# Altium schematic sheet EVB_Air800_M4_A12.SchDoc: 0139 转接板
size 840 x 594 mm; REV: 1.0; DESIGNER: LouKangHua
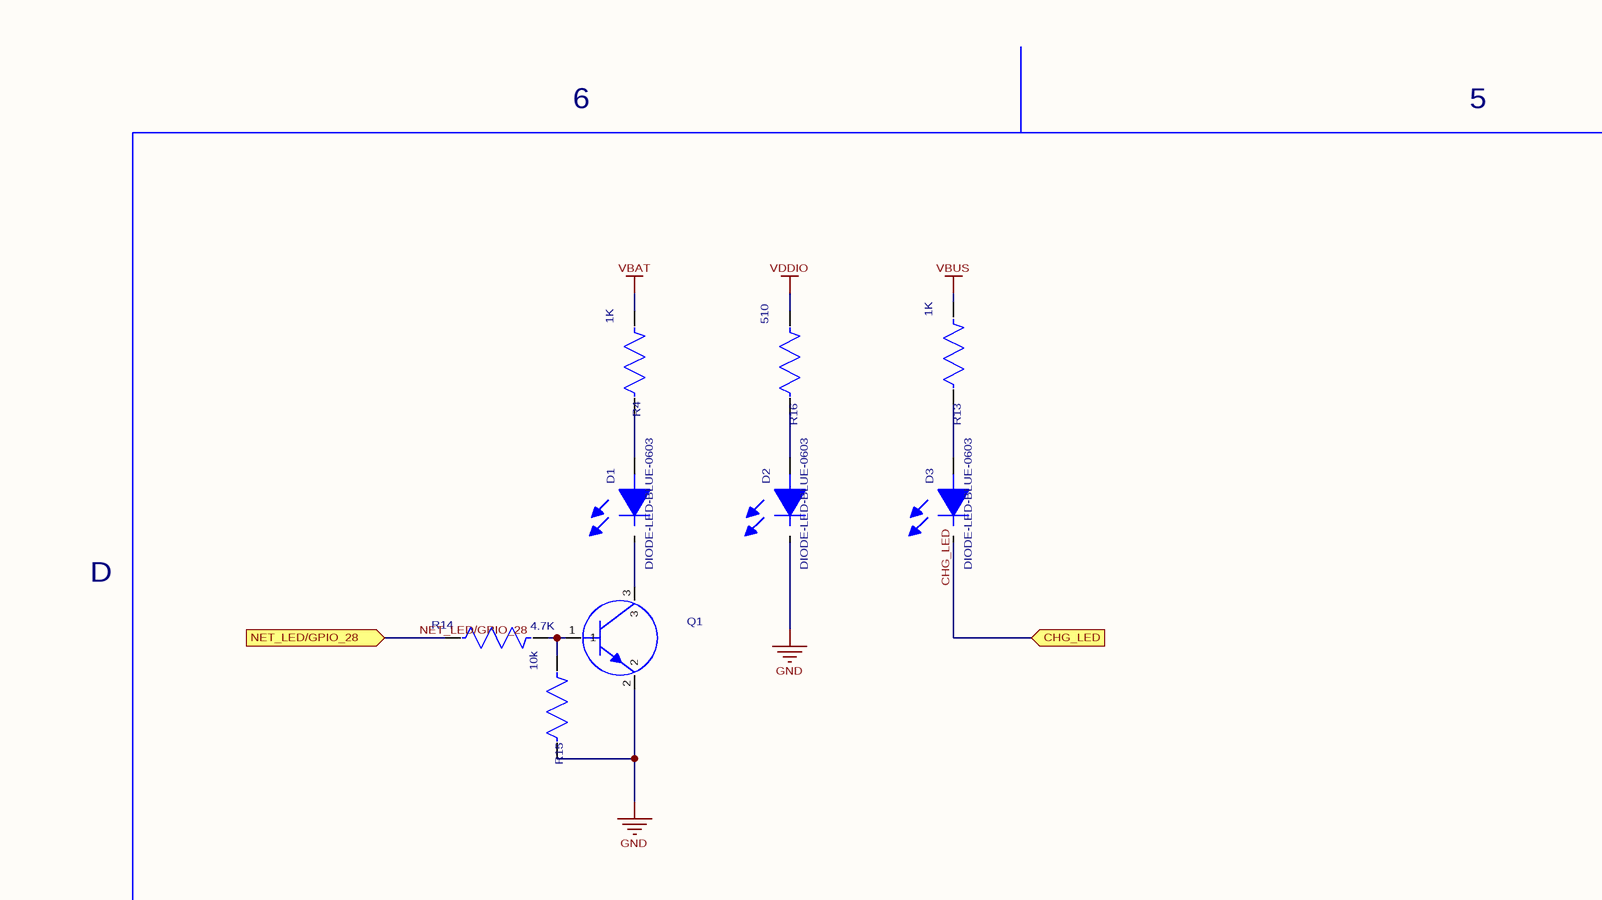
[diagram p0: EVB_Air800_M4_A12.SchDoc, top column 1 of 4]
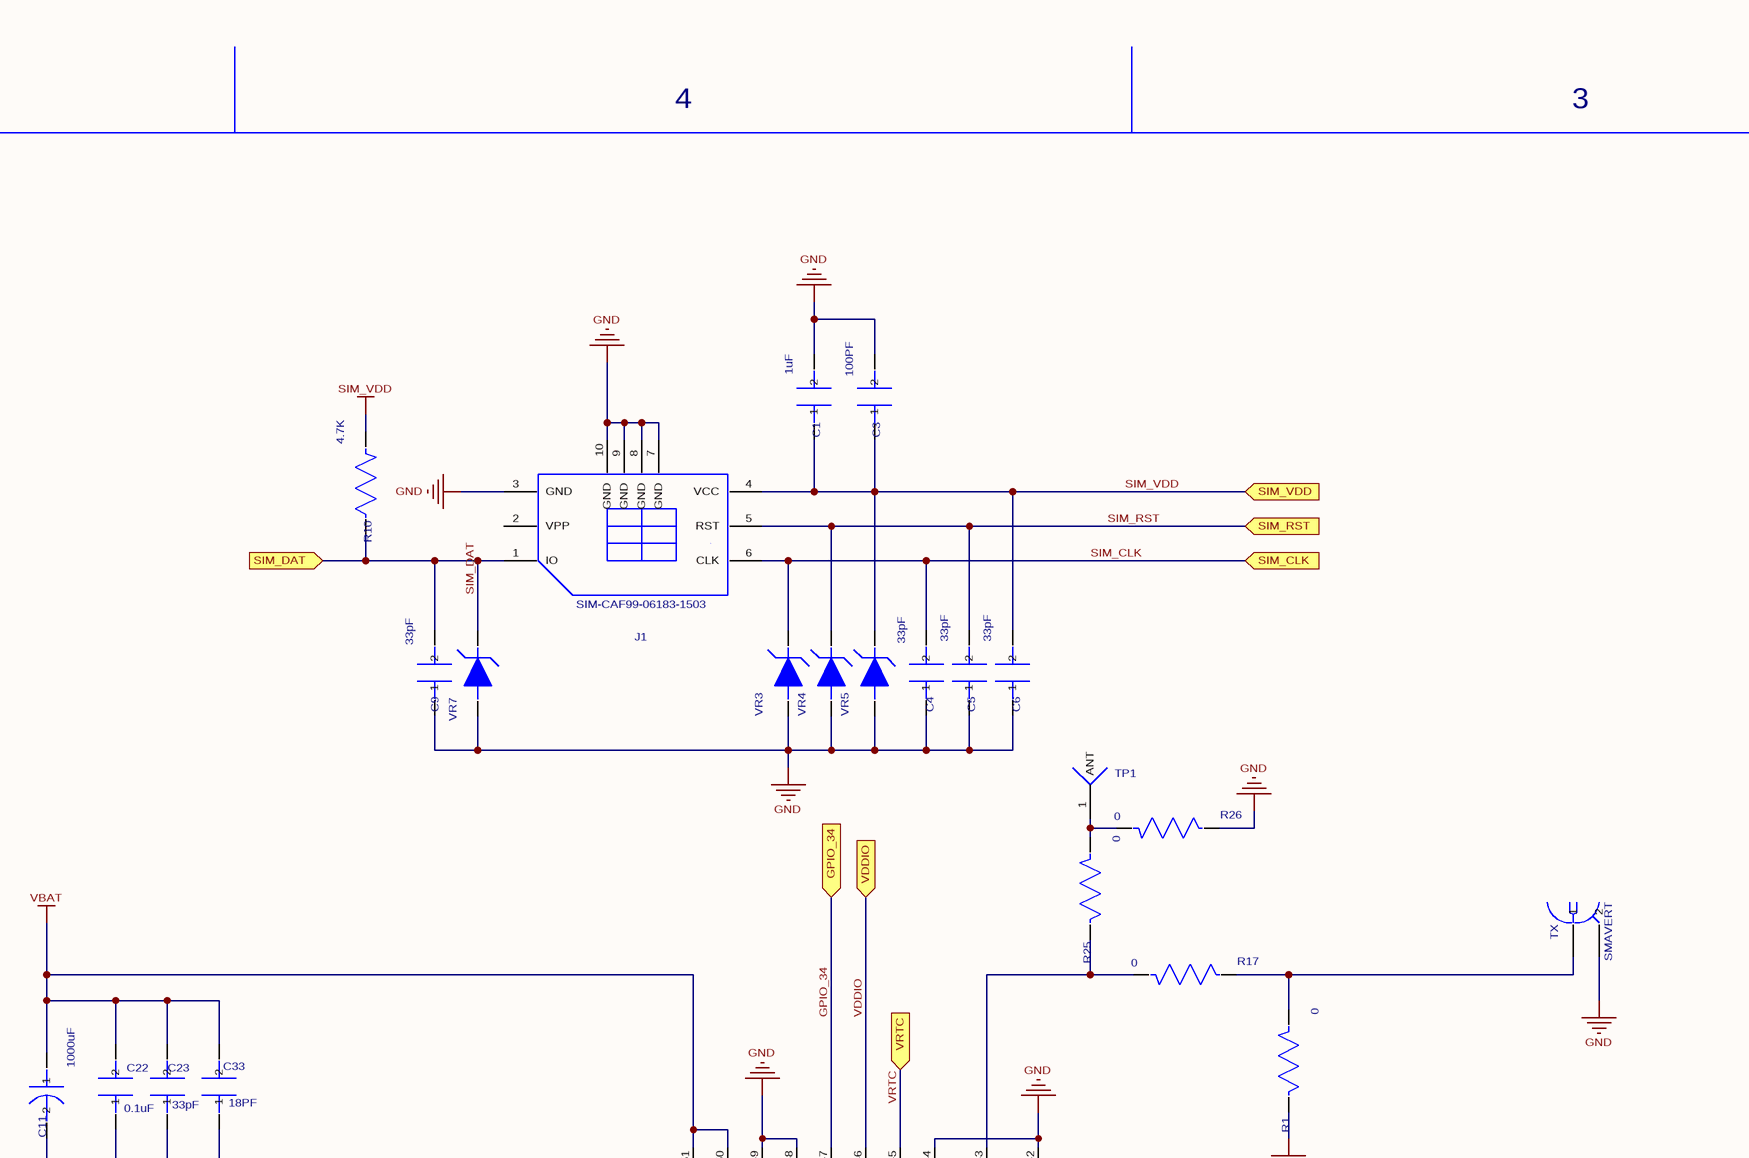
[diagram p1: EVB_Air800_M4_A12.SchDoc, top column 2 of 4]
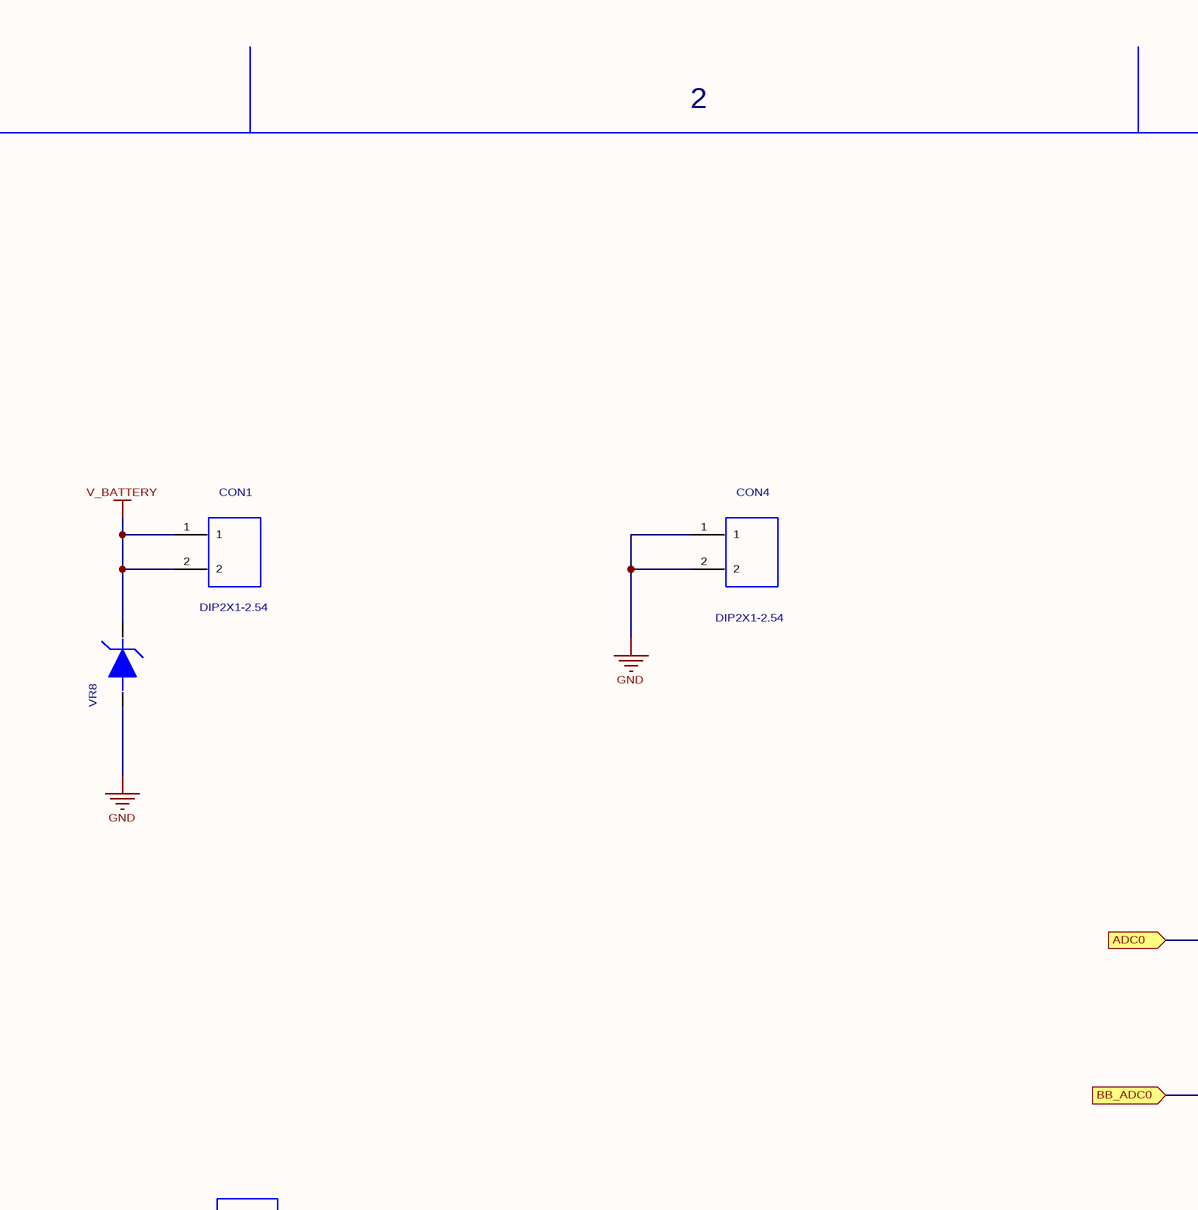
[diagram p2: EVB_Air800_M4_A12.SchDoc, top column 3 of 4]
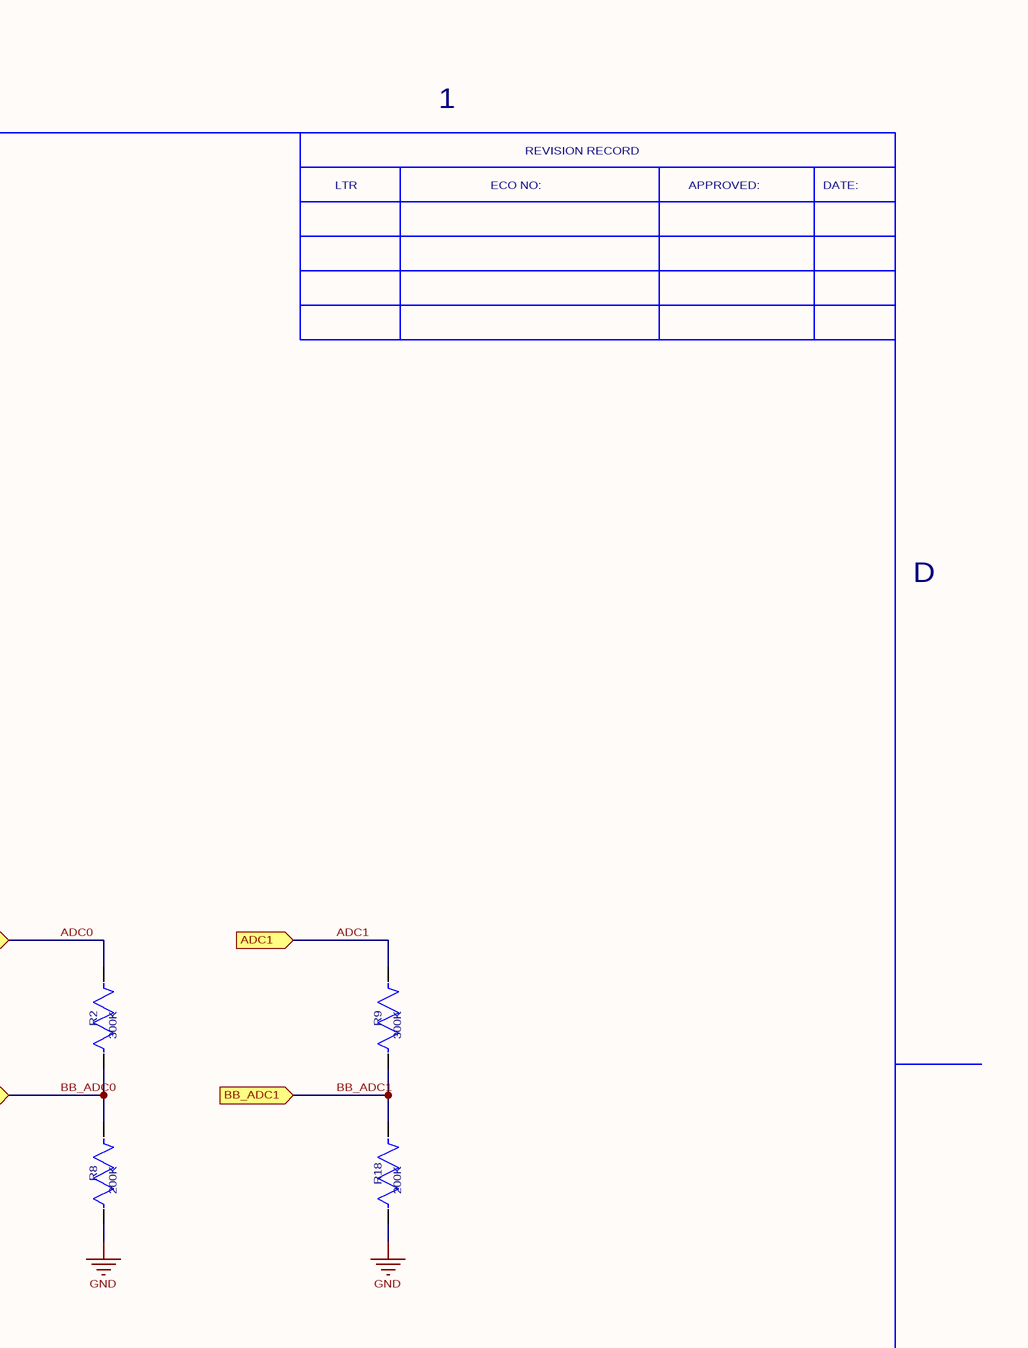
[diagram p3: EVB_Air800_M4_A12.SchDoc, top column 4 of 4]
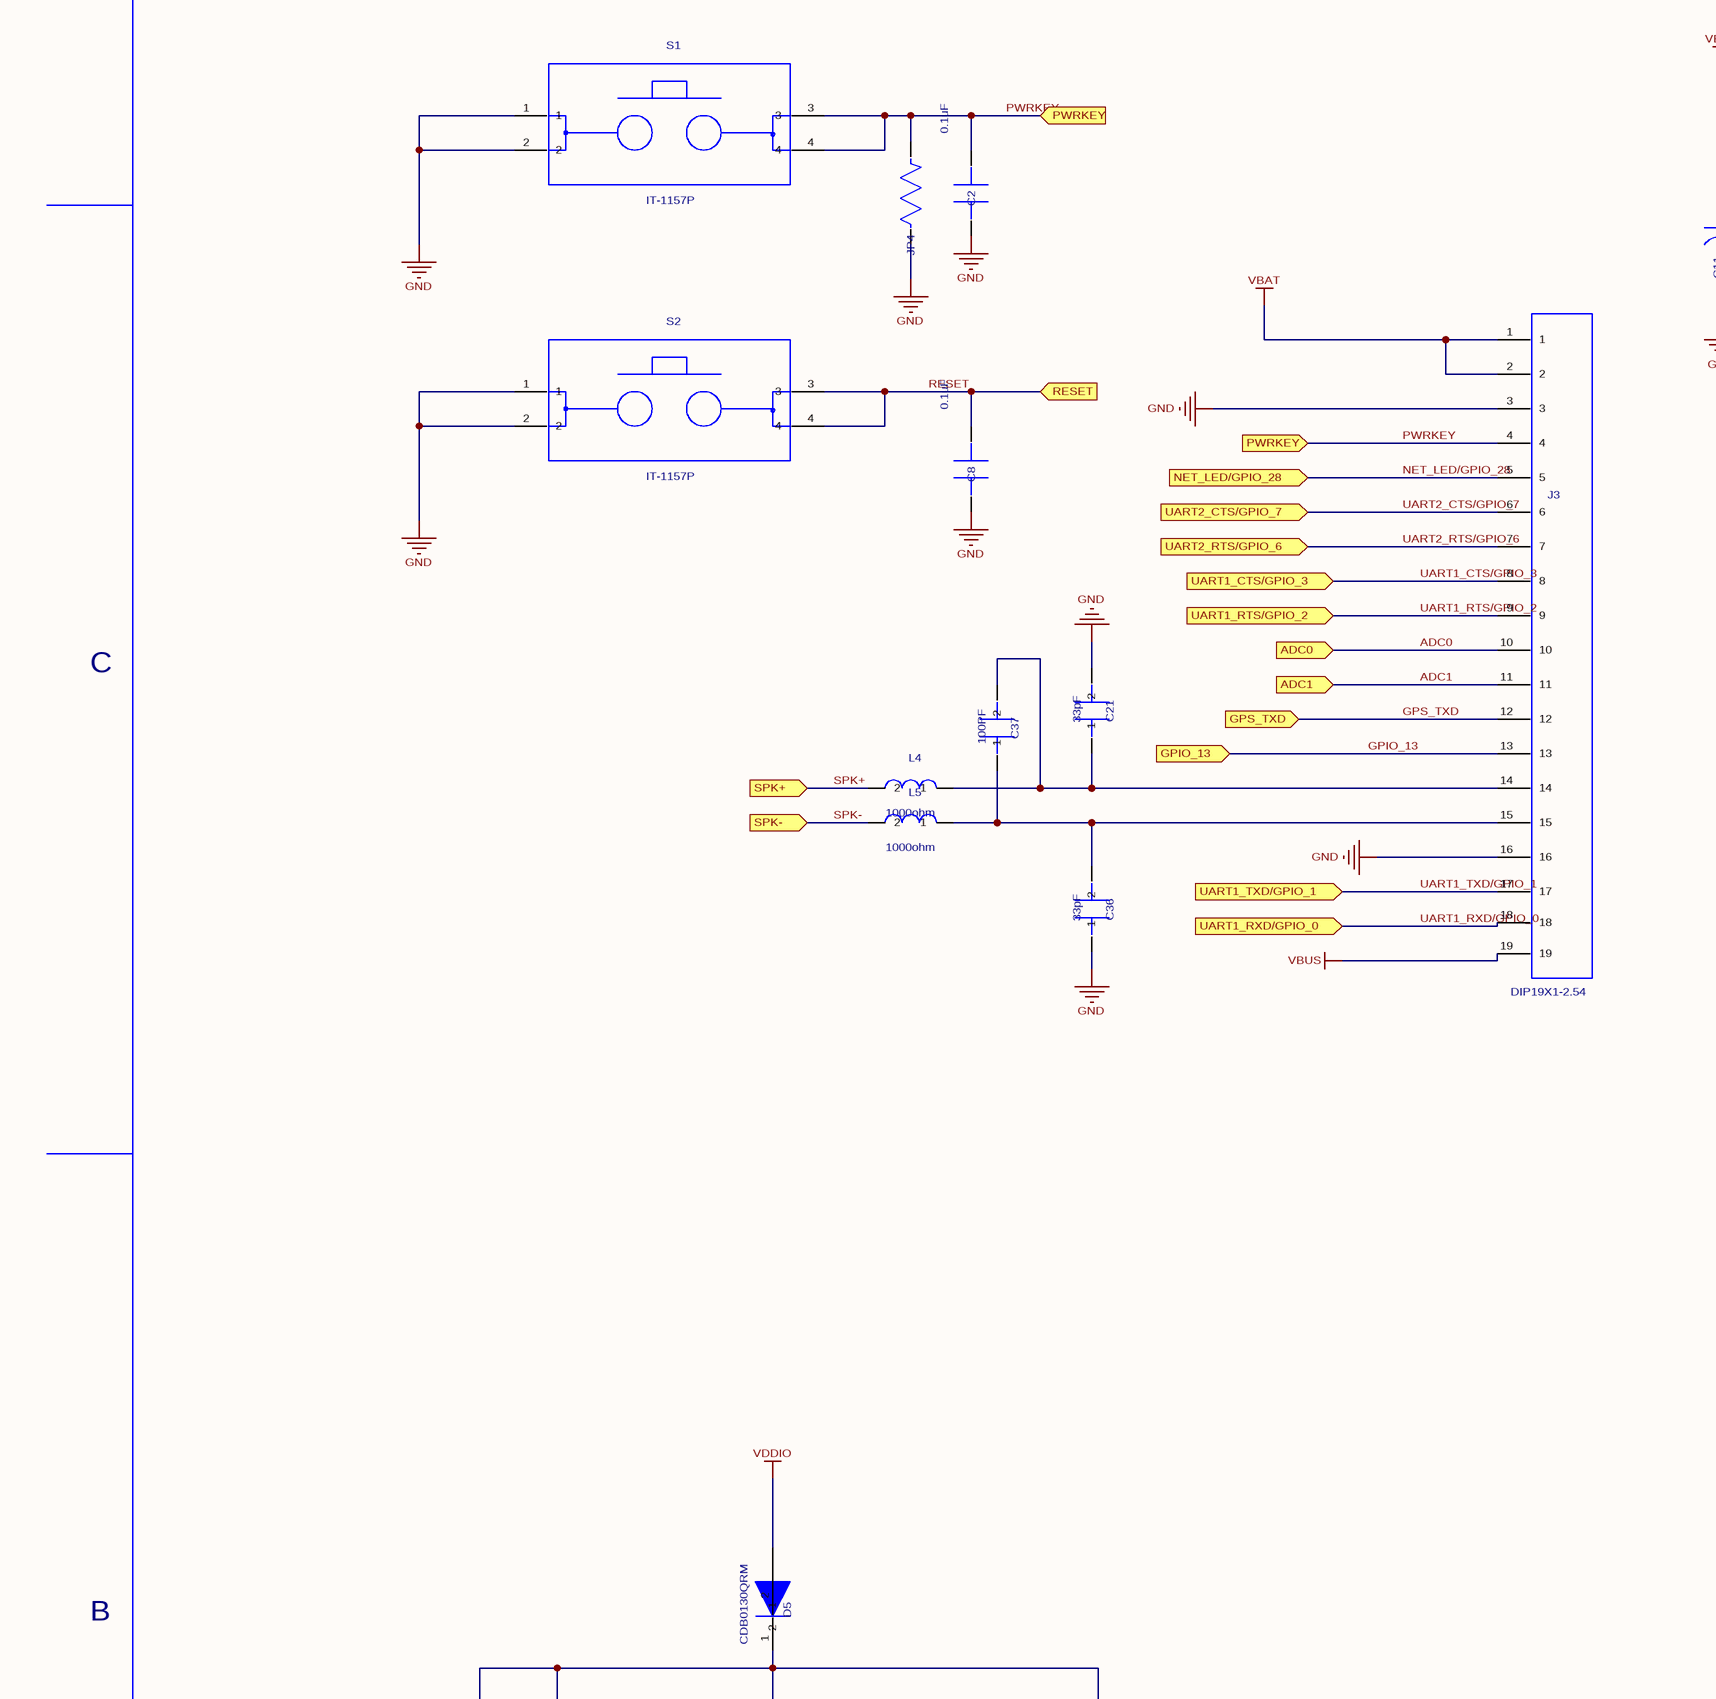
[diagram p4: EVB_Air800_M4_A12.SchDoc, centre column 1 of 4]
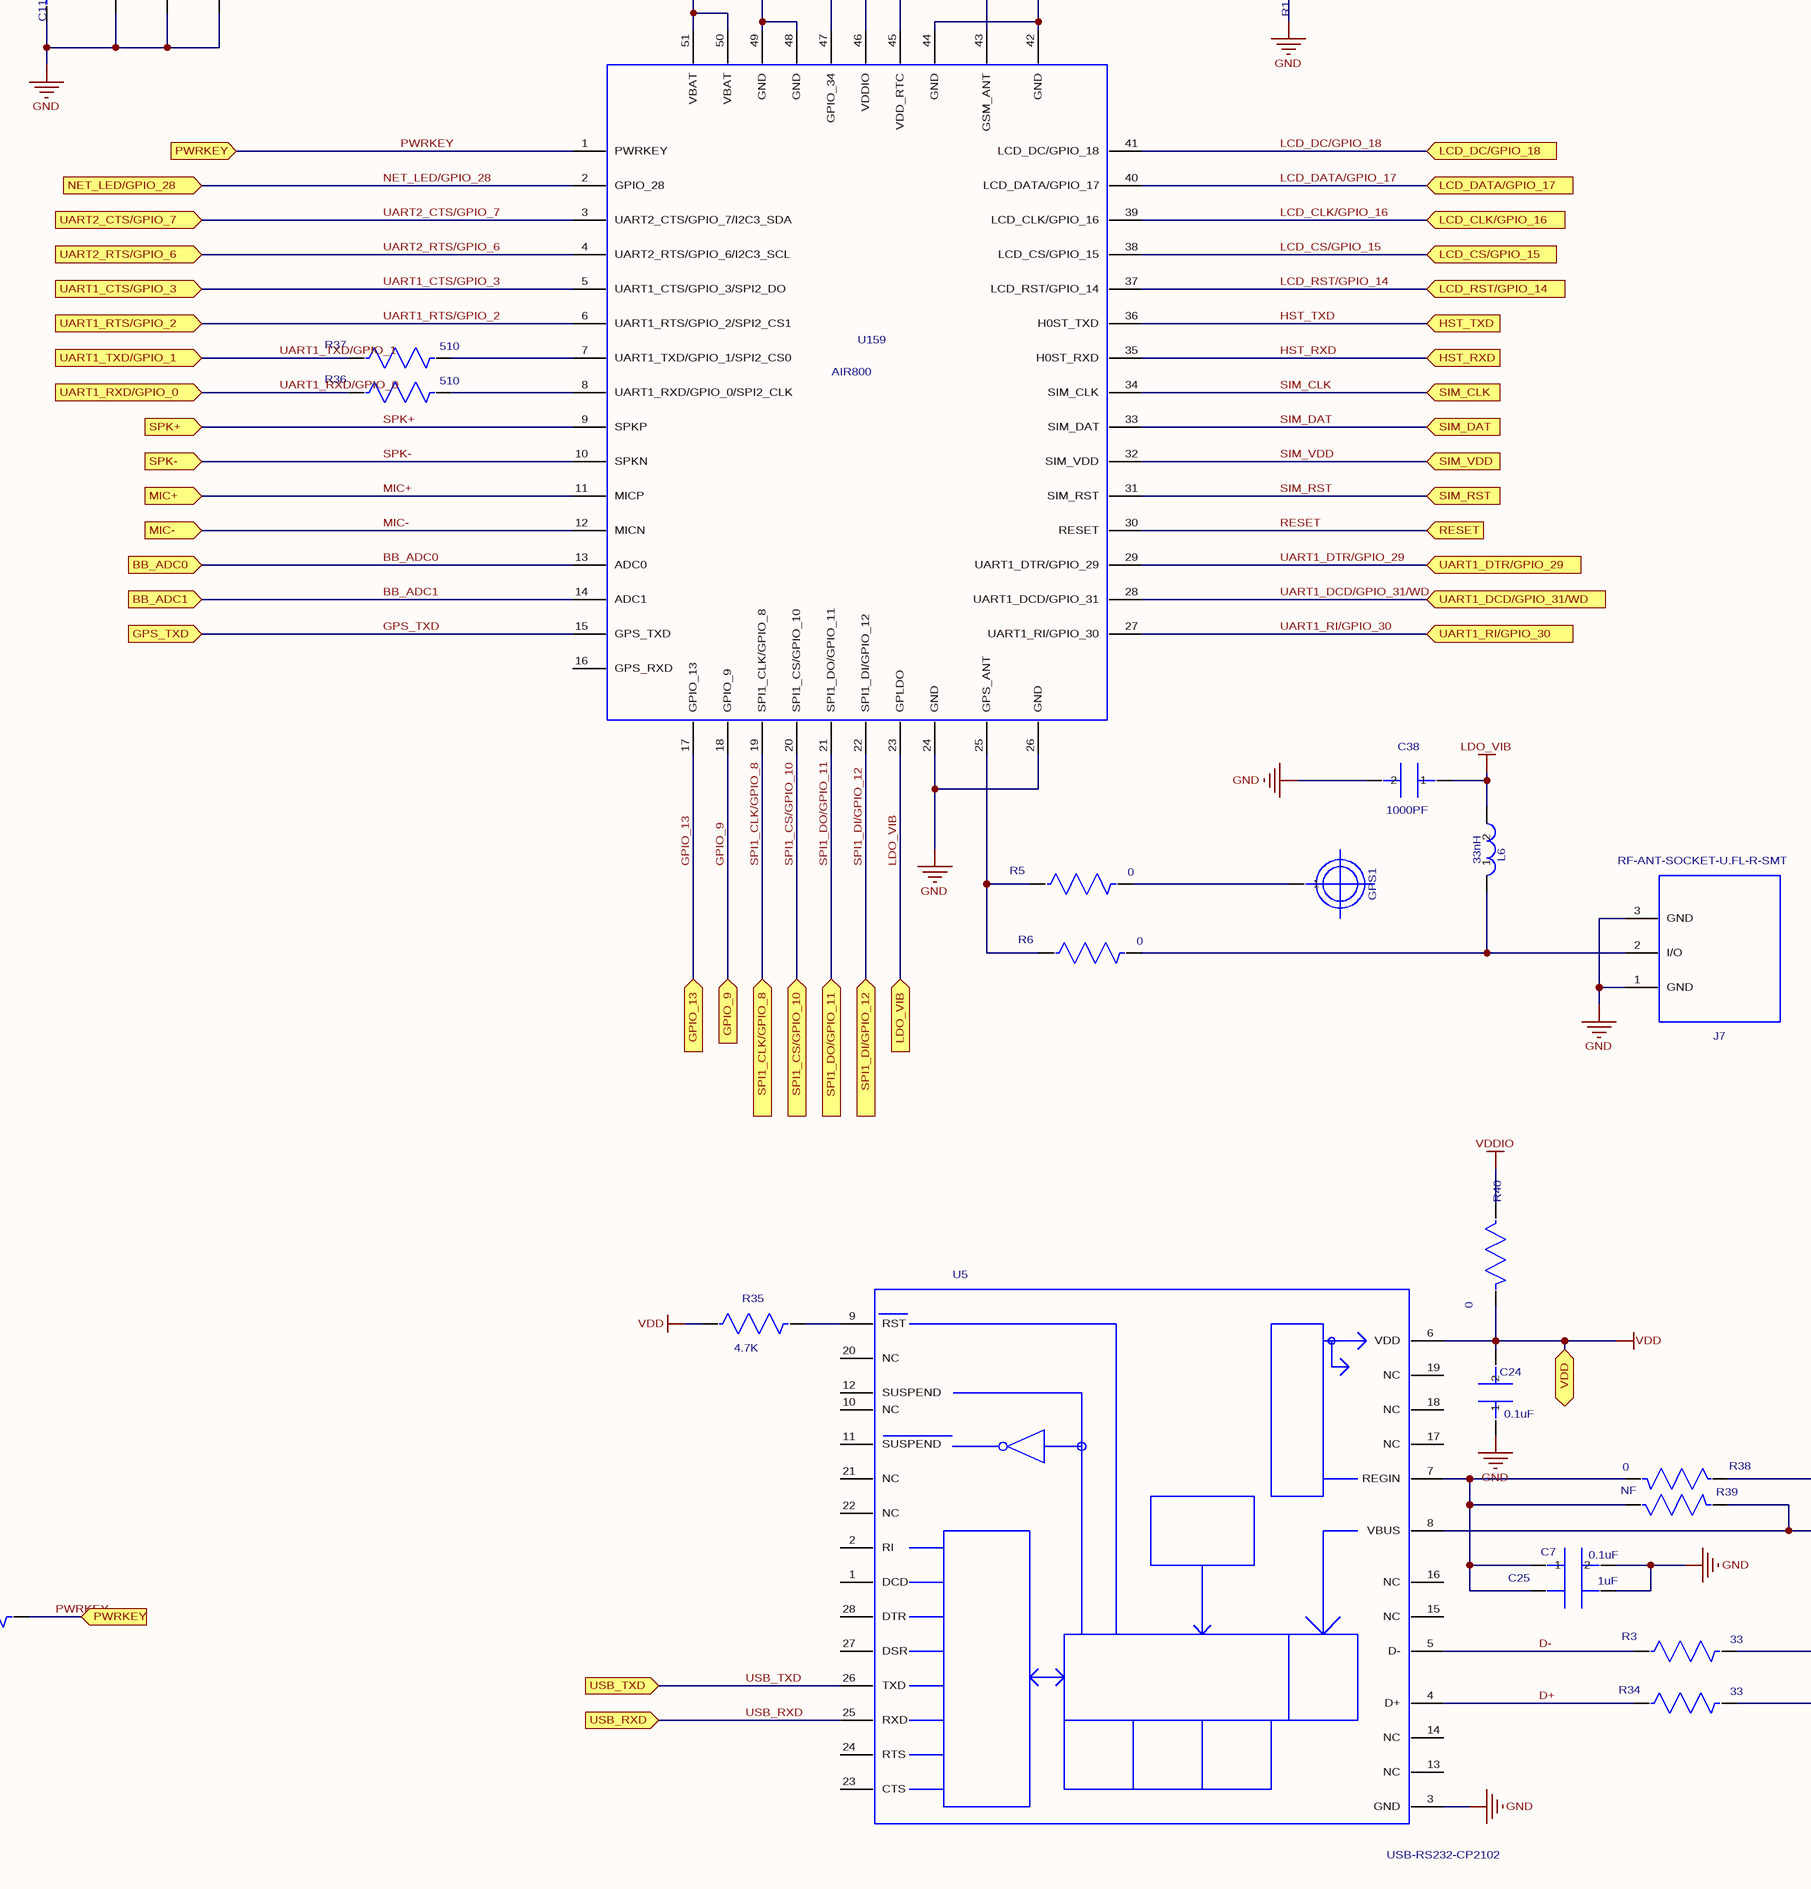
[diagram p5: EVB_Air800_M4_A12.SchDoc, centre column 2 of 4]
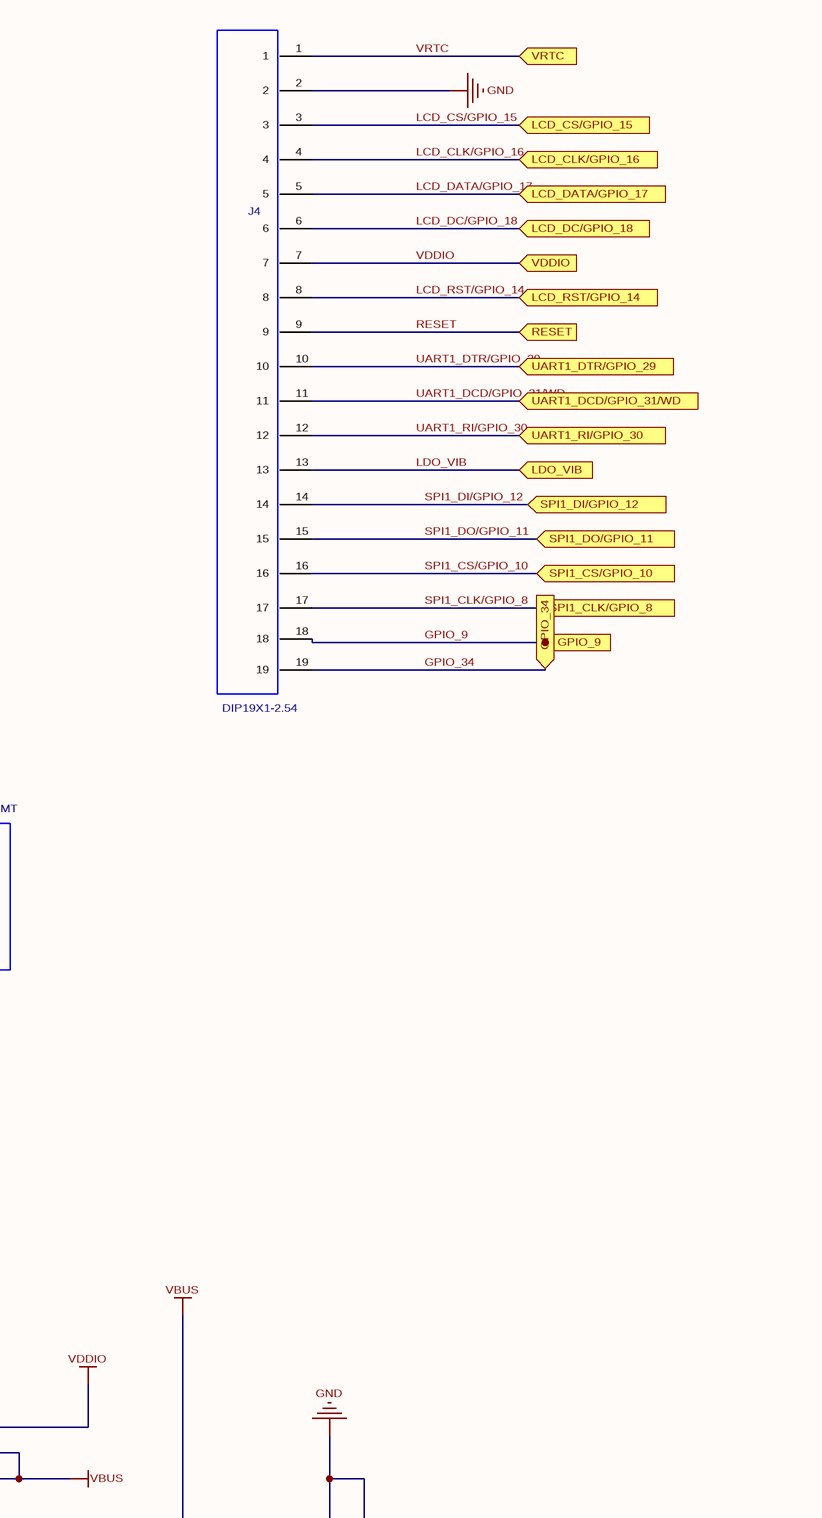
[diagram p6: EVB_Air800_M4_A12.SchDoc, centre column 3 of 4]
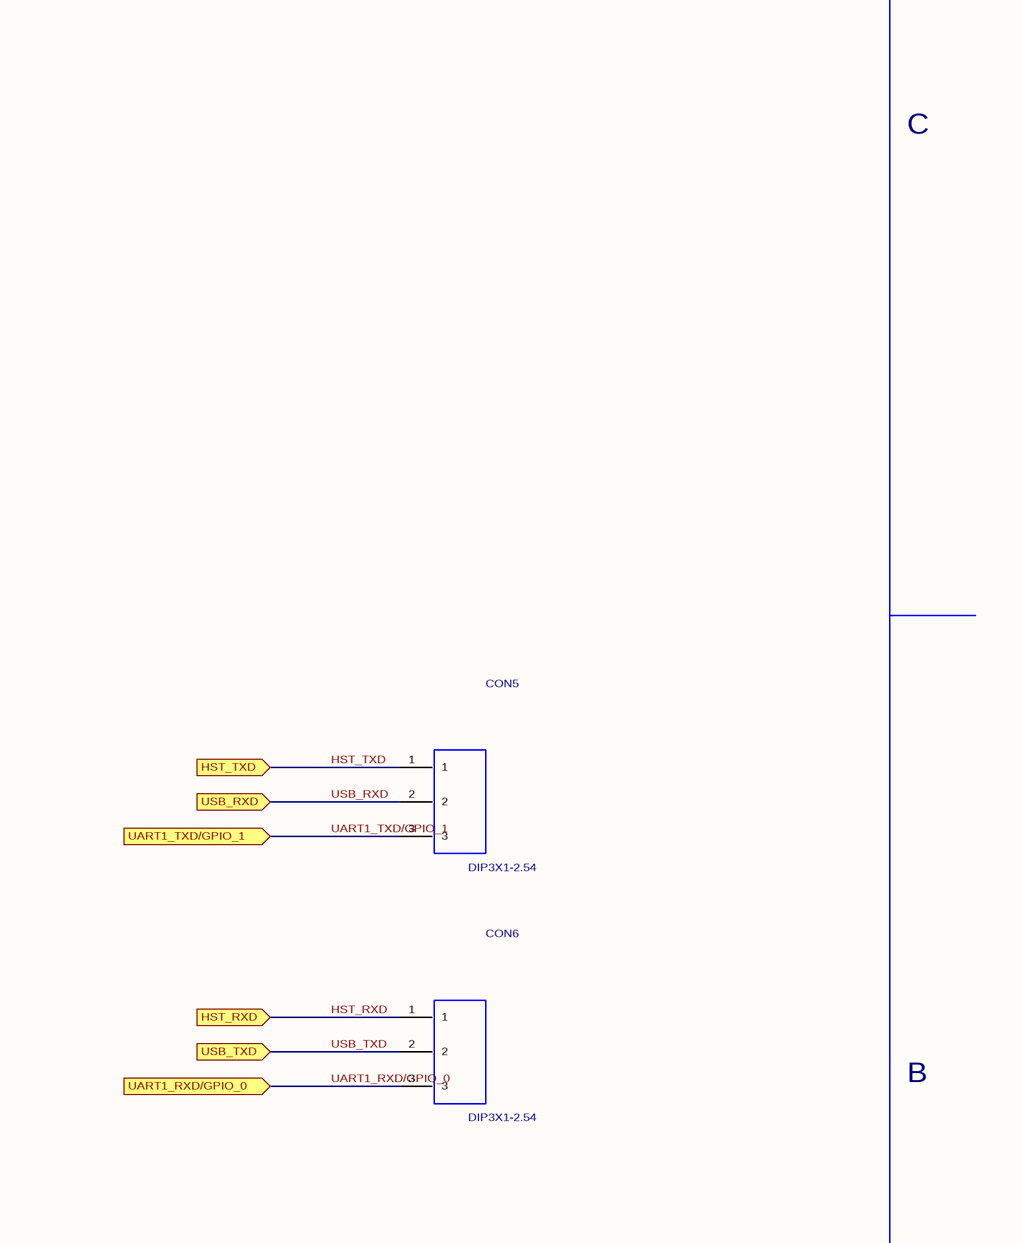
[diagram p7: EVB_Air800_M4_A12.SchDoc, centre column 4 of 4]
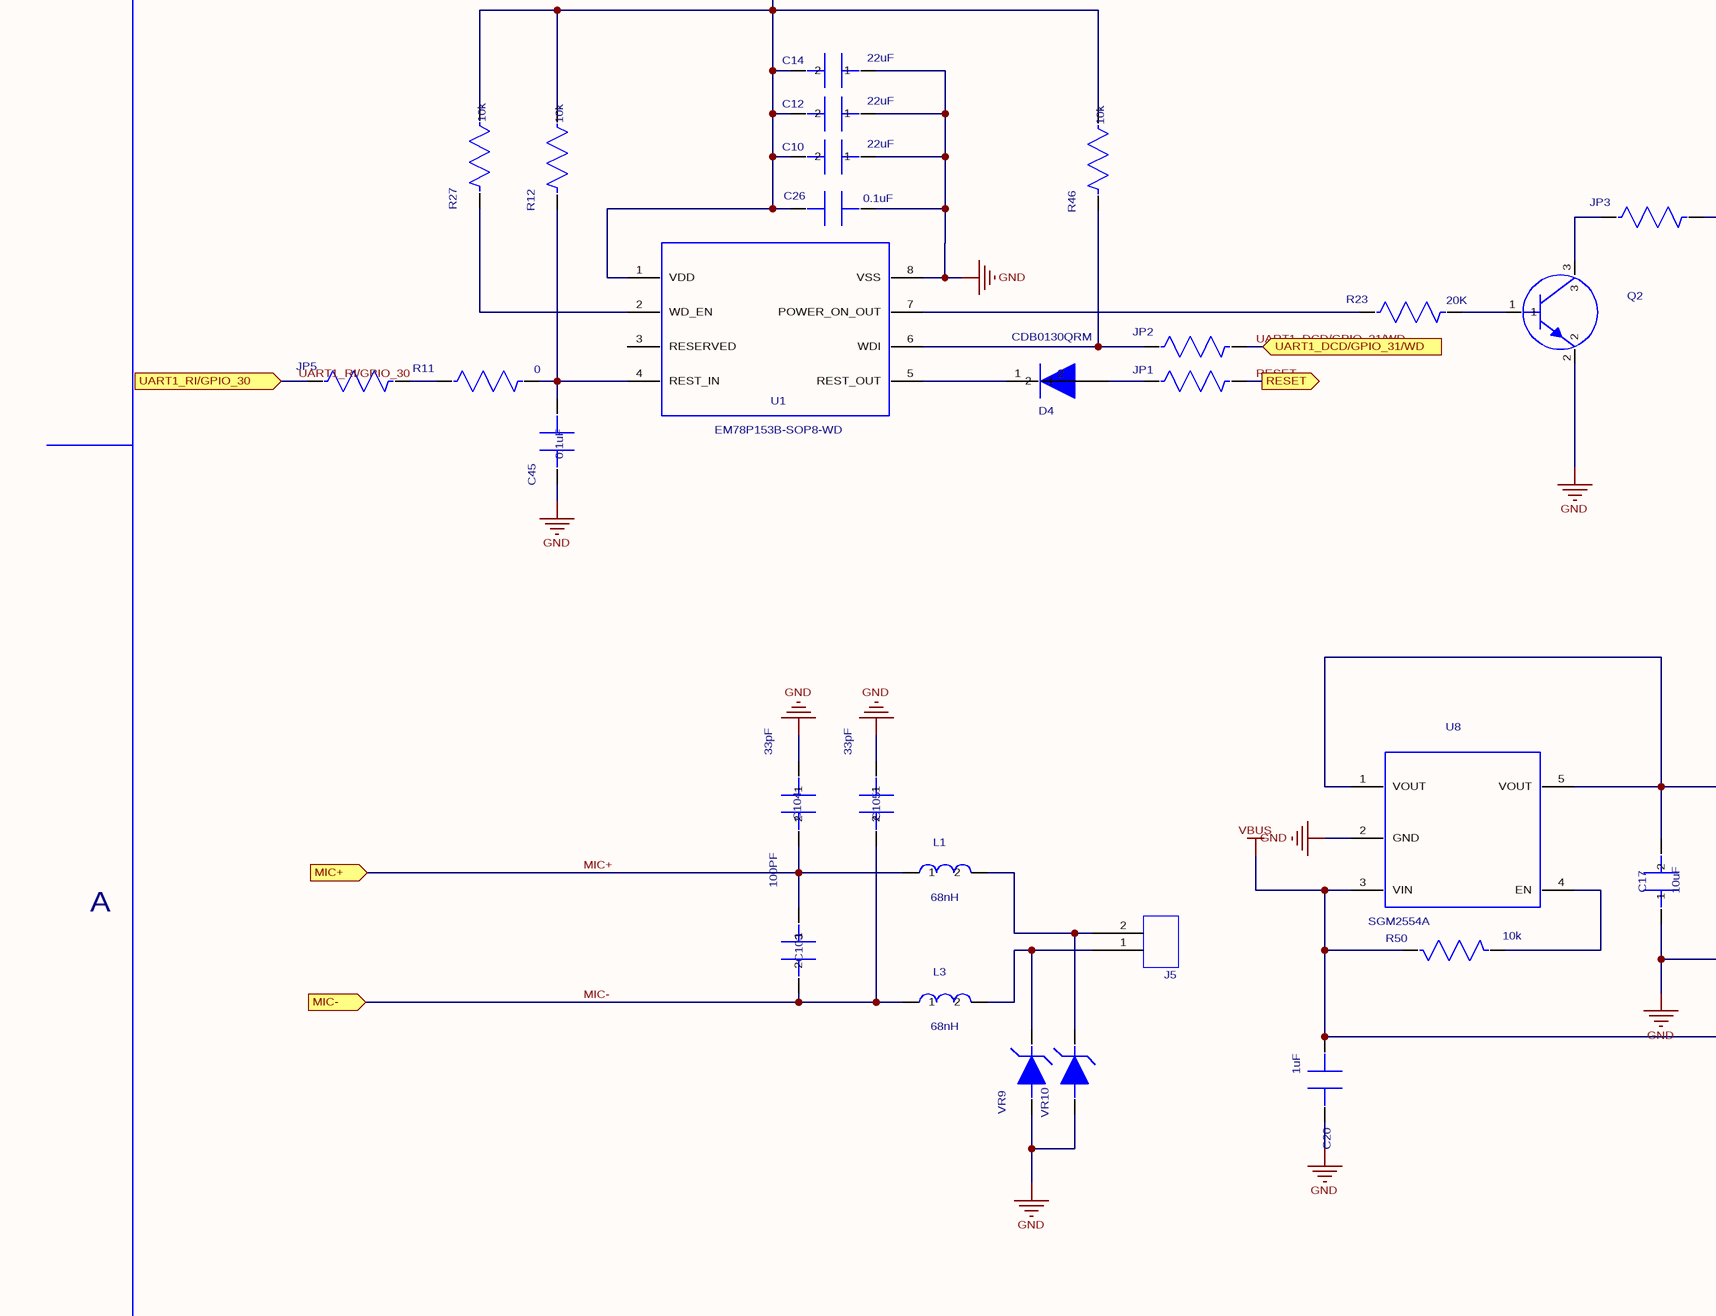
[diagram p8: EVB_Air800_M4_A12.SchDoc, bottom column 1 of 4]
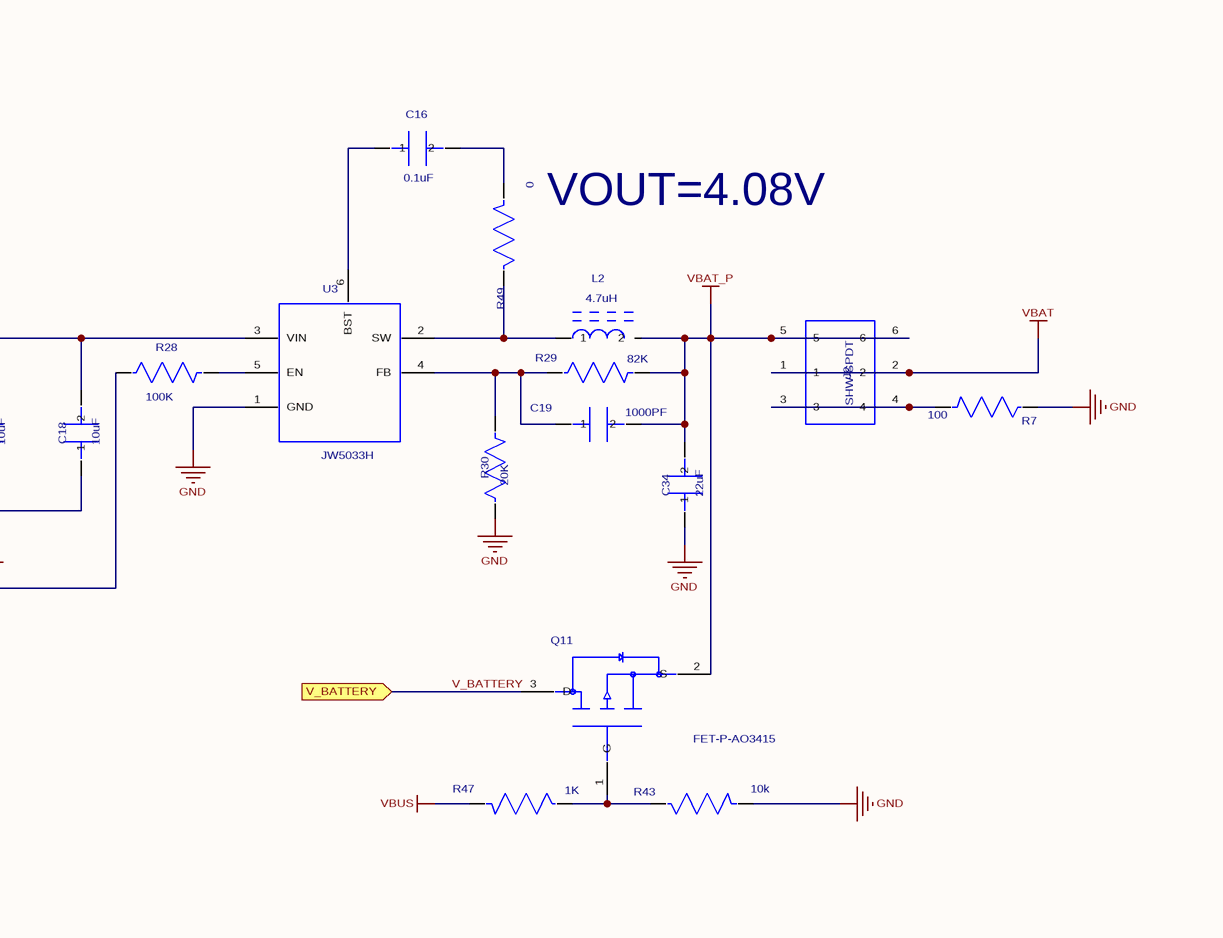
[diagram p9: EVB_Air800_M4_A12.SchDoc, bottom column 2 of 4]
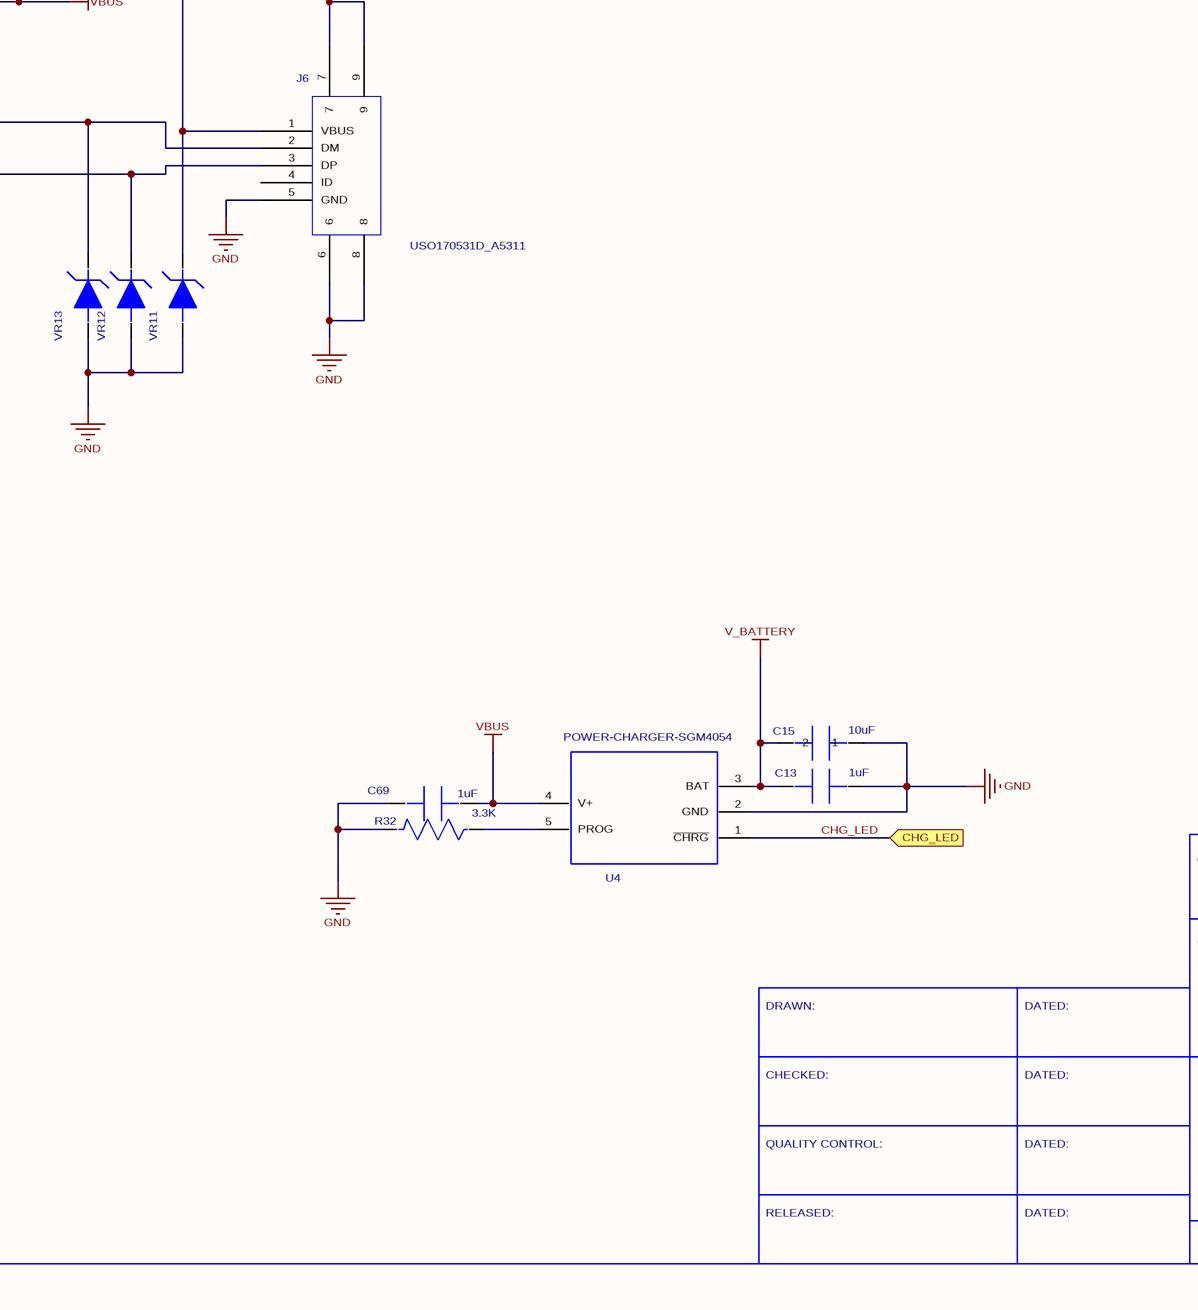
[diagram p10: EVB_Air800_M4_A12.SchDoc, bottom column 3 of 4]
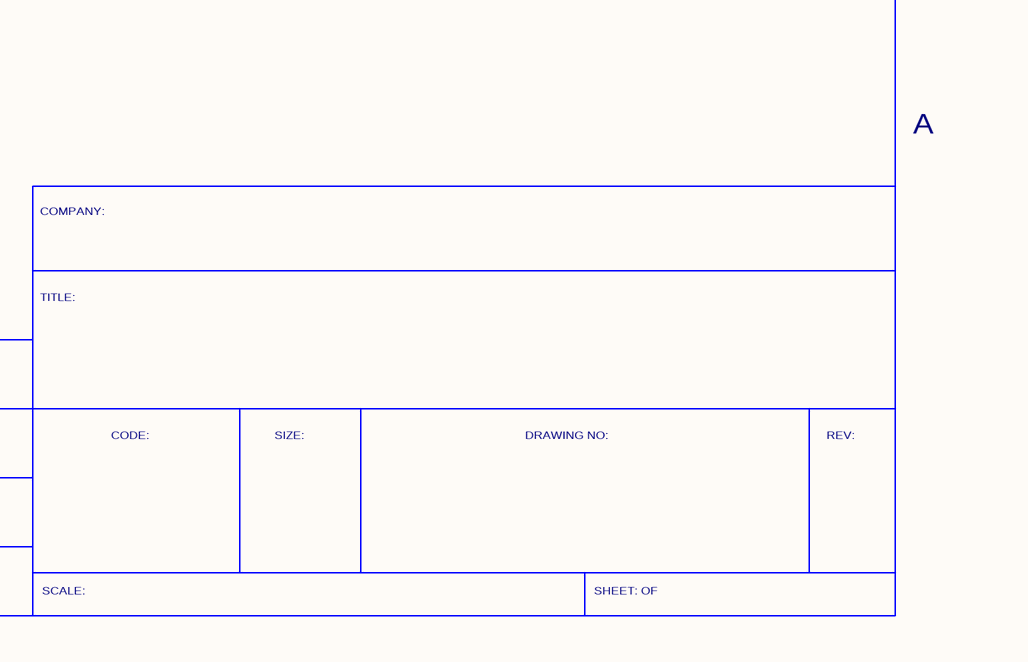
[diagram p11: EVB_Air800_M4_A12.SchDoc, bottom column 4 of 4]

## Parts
C1  value 1uF  [SC0402]  (hidden comment: CAP-1UF-0402-X5R)
C2  value 0.1uF  [SC0402]  (hidden comment: CAP-0.1UF-0402-X5R-10V)
C3  value 100PF  [SC0402]  (hidden comment: CAP-100PF-0402-C0G)
C4  value 33pF  [SC0402]  (hidden comment: CAP-33PF-0402-C0G)
C5  value 33pF  [SC0402]  (hidden comment: CAP-33PF-0402-C0G)
C6  value 33pF  [SC0402]  (hidden comment: CAP-33PF-0402-C0G)
C7  value 0.1uF  [SC0402]  (hidden comment: CAP-0.1UF-0402-X7R)
C8  value 0.1uF  [SC0402]  (hidden comment: CAP-0.1UF-0402-X5R-10V)
C9  value 33pF  [SC0402]  (hidden comment: CAP-33PF-0402-C0G)
C10  value 22uF  [SC0603]  (hidden comment: CAP-4.7UF-0603-X5R)
C11  value 1000uF  [CAP-AL-1000UF-10.4X10.4]  (hidden comment: CAP-AL-1000UF-10.4X10.4)
C12  value 22uF  [SC0603]  (hidden comment: CAP-4.7UF-0603-X5R)
C13  value 1uF  [SC0402]  (hidden comment: CAP-1UF-0402-X5R)
C14  value 22uF  [SC0603]  (hidden comment: CAP-4.7UF-0603-X5R)
C15  value 10uF  [SC0402]  (hidden comment: CAP-2.2UF-0402-X5R)
C16  value 0.1uF  [SC0402]  (hidden comment: CAP-0.1UF-0402-X5R-10V)
C17  value 10uF  [SC0603]  (hidden comment: CAP-4.7UF-0603-X5R)
C18  value 10uF  [SC0603]  (hidden comment: CAP-4.7UF-0603-X5R)
C19  value 1000PF  [SC0402]  (hidden comment: CAP-1000PF-0402-X7R)
C20  value 1uF  [SC0402]  (hidden comment: CAP-1UF-0402-X5R)
C21  value 33pF  [SC0402]  (hidden comment: CAP-33PF-0402-C0G)
C22  value 0.1uF  [SC0402]  (hidden comment: CAP-0.1UF-0402-X7R)
C23  value 33pF  [SC0402]  (hidden comment: CAP-33PF-0402-C0G)
C24  value 0.1uF  [SC0402]  (hidden comment: CAP-0.1UF-0402-X5R-10V)
C25  value 1uF  [SC0402]  (hidden comment: CAP-1UF-0402-X5R)
C26  value 0.1uF  [SC0402]  (hidden comment: CAP-0.1UF-0402-X5R-10V)
C33  value 18PF  [SC0402]  (hidden comment: CAP-18PF-0402-C0G)
C34  value 22uF  [SC0603]  (hidden comment: CAP-4.7UF-0603-X5R)
C36  value 33pF  [SC0402]  (hidden comment: CAP-33PF-0402-C0G)
C37  value 100PF  [SC0402]  (hidden comment: CAP-100PF-0402-C0G)
C38  value 1000PF  [SC0402]  (hidden comment: CAP-1000PF-0402-X7R)
C45  value 0.1uF  [SC0402]  (hidden comment: CAP-0.1UF-0402-X5R-10V)
C69  value 1uF  [SC0402]  (hidden comment: CAP-1UF-0402-X5R)
C103  value 100PF  [SC0402]  (hidden comment: CAP-100PF-0402-C0G)
C104  value 33pF  [SC0402]  (hidden comment: CAP-33PF-0402-C0G)
C105  value 33pF  [SC0402]  (hidden comment: CAP-33PF-0402-C0G)
CON1  DIP2X1-2.54  [DIP2X1-2.54]
CON4  DIP2X1-2.54  [DIP2X1-2.54]
CON5  DIP3X1-2.54  [DIP3X1-2.54]
CON6  DIP3X1-2.54  [DIP3X1-2.54]
D1  DIODE-LED-BLUE-0603  [LED-0603]
D2  DIODE-LED-BLUE-0603  [LED-0603]
D3  DIODE-LED-BLUE-0603  [LED-0603]
D4  CDB0130QRM  [ESD-TVS-UM5079]
D5  CDB0130QRM  [ESD-TVS-UM5079]
GPS1  DAS1575R25C54  [DAS1575R25C54]  (value not drawn)
J1  SIM-CAF99-06183-1503  [SIM-CAF99-06183-1503]
J2  SHW-SPDT  [SHW-SPDT]
J3  DIP19X1-2.54  [DIP19X1-2.54]
J4  DIP19X1-2.54  [DIP19X1-2.54]
J5  MIC_A5311  [MIC_A5311]  (value not drawn)
J6  USO170531D_A5311  [USO170531D_A5311]
J7  RF-ANT-SOCKET-U.FL-R-SMT  [RF-ANT-SOCKET-U.FL-R-SMT]
JP1  RESISTANCE  [R60L08]  (value not drawn)
JP2  RESISTANCE  [R60L08]  (value not drawn)
JP3  RESISTANCE  [R60L08]  (value not drawn)
JP4  RESISTANCE  [R60L08]  (value not drawn)
JP5  RESISTANCE  [R60L08]  (value not drawn)
L1  value 68nH  [SL0402]  (hidden comment: IND-MULT-68NH-0402)
L2  value 4.7uH  [MRSC252A12-4R7W-N]  (hidden comment: MRSC252A12-4R7W-N)
L3  value 68nH  [SL0402]  (hidden comment: IND-MULT-68NH-0402)
L4  value 1000ohm  [SL0402]  (hidden comment: BEAD-1000OHM-0402)
L5  value 1000ohm  [SL0402]  (hidden comment: BEAD-1000OHM-0402)
L6  value 33nH  [SL0402]  (hidden comment: IND-MULT-33NH-0402-MURATA)
Q1  TRIODE-NPN-MMBT3904  [SOT-23(MMBT3904)]  (value not drawn)
Q2  TRIODE-NPN-MMBT3904  [SOT-23(MMBT3904)]  (value not drawn)
Q11  FET-P-AO3415  [SOT-23]
R1  value 0  [SR0402]  (hidden comment: RES-0-0402)
R2  value 300K  [SR0402]  (hidden comment: RES-300K-+/-1%-0402)
R3  value 33  [SR0402]  (hidden comment: RES-33-0402)
R4  value 1K  [SR0402]  (hidden comment: RES-1K-0402)
R5  value 0  [SR0402]  (hidden comment: RES-0-0402)
R6  value 0  [SR0402]  (hidden comment: RES-0-0402)
R7  value 100  [SR0402]  (hidden comment: RES-100-0402)
R8  value 200K  [SR0402]  (hidden comment: RES-200K-+-1%-0402)
R9  value 300K  [SR0402]  (hidden comment: RES-300K-+/-1%-0402)
R10  value 4.7K  [SR0402]  (hidden comment: RES-4.7K-0402)
R11  value 0  [SR0402]  (hidden comment: RES-0-0402)
R12  value 10k  [SR0402]  (hidden comment: RES-10K-0402)
R13  value 1K  [SR0402]  (hidden comment: RES-1K-0402)
R14  value 4.7K  [SR0402]  (hidden comment: RES-4.7K-0402)
R15  value 10k  [SR0402]  (hidden comment: RES-10K-0402)
R16  value 510  [SR0402]  (hidden comment: RES-510-0402)
R17  value 0  [SR0402]  (hidden comment: RES-0-0402)
R18  value 200K  [SR0402]  (hidden comment: RES-200K-+-1%-0402)
R23  value 20K  [SR0402]  (hidden comment: RES-20K-+/-5%-0402)
R25  value 0  [SR0402]  (hidden comment: RES-0-0402)
R26  value 0  [SR0402]  (hidden comment: RES-0-0402)
R27  value 10k  [SR0402]  (hidden comment: RES-10K-0402)
R28  value 100K  [SR0402]  (hidden comment: RES-100K-0402)
R29  value 82K  [SR0402]  (hidden comment: RES-82K-+-1%-0402)
R30  value 20K  [SR0402]  (hidden comment: RES-20K-+/-1%-0402)
R32  value 3.3K  [SR0402]  (hidden comment: RES-3.3K-0402)
R34  value 33  [SR0402]  (hidden comment: RES-33-0402)
R35  value 4.7K  [SR0402]  (hidden comment: RES-4.7K-0402)
R36  value 510  [SR0402]  (hidden comment: RES-510-0402)
R37  value 510  [SR0402]  (hidden comment: RES-510-0402)
R38  value 0  [SR0402]  (hidden comment: RES-0-0402)
R39  value NF  [SR0402-NF]  (hidden comment: RES-0402-NF)
R40  value 0  [SR0402]  (hidden comment: RES-0-0402)
R43  value 10k  [SR0402]  (hidden comment: RES-10K-0402)
R46  value 10k  [SR0402]  (hidden comment: RES-10K-0402)
R47  value 1K  [SR0402]  (hidden comment: RES-1K-0402)
R49  value 0  [SR0402]  (hidden comment: RES-0-0402)
R50  value 10k  [SR0402]  (hidden comment: RES-10K-0402)
S1  IT-1157P  [IT-1157P]
S2  IT-1157P  [IT-1157P]
TP1  ANT-02  [ANT-02]  (value not drawn)
TX  SMAVERT  [SMA-V]
U1  EM78P153B-SOP8-WD  [EM78P153B-SOP8]
U3  JW5033H  [JW5033S]
U4  POWER-CHARGER-SGM4054  [SOT-235]
U5  USB-RS232-CP2102  [USB-DRIVER-CP2102]
U8  SGM2554A  [SOT-235]
U159  AIR800  [AIR800]
VR3  ESD-TVS-UM5079  [ESD-TVS-UM5079]  (value not drawn)
VR4  ESD-TVS-UM5079  [ESD-TVS-UM5079]  (value not drawn)
VR5  ESD-TVS-UM5079  [ESD-TVS-UM5079]  (value not drawn)
VR7  ESD-TVS-UM5079  [ESD-TVS-UM5079]  (value not drawn)
VR8  ESD-TVS-UM5079  [ESD-TVS-UM5079]  (value not drawn)
VR9  ESD-TVS-UM5079  [ESD-TVS-UM5079]  (value not drawn)
VR10  ESD-TVS-UM5079  [ESD-TVS-UM5079]  (value not drawn)
VR11  ESD-TVS-UM5079  [ESD-TVS-UM5079]  (value not drawn)
VR12  ESD-TVS-UM5079  [ESD-TVS-UM5079]  (value not drawn)
VR13  ESD-TVS-UM5079  [ESD-TVS-UM5079]  (value not drawn)

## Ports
ADC0, ADC1, BB_ADC0, BB_ADC1, CHG_LED, GPIO_9, GPIO_13, GPIO_34, GPS_TXD, HST_RXD, HST_TXD, LCD_CLK/GPIO_16, LCD_CS/GPIO_15, LCD_DATA/GPIO_17, LCD_DC/GPIO_18, LCD_RST/GPIO_14, LDO_VIB, MIC+, MIC-, NET_LED/GPIO_28, PWRKEY, RESET, RESET (out), SIM_CLK, SIM_DAT, SIM_RST, SIM_VDD, SPI1_CLK/GPIO_8, SPI1_CS/GPIO_10, SPI1_DI/GPIO_12, SPI1_DO/GPIO_11, SPK+, SPK-, UART1_CTS/GPIO_3, UART1_DCD/GPIO_31/WD, UART1_DTR/GPIO_29, UART1_RI/GPIO_30, UART1_RTS/GPIO_2, UART1_RXD/GPIO_0, UART1_TXD/GPIO_1, UART2_CTS/GPIO_7, UART2_RTS/GPIO_6, USB_RXD, USB_TXD, V_BATTERY, VDD (bidir), VDDIO, VRTC

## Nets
GND: C1.2 C2.2 C3.2 C4.1 C5.1 C6.1 C7.2 C8.2 C9.1 C10.1 C11.2 C12.1 C13.2 C14.1 C15.1 C17.1 C18.1 C20.1 C21.2 C22.1 C23.1 C24.1 C25.2 C26.2 C33.1 C34.1 C36.1 C38.2 C45.1 C69.1 C104.1 C105.1 CON4.1 CON4.2 D2.2 J1.3(GND) J1.7(GND) J1.8(GND) J1.9(GND) J1.10(GND) J3.3 J3.16 J4.2 J6.5(GND) J6.6 J6.7 J6.8 J6.9 J6.10(GND) J6.11(GND) J7.1(GND) J7.3(GND) JP4.1 Q1.2 Q2.2 R1.1 R7.1 R8.1 R15.1 R18.1 R26.1 R30.1 R32.2 R43.2 S1.1 S1.2 S1.5(GND) S2.1 S2.2 S2.5(GND) TX.2 TX.3(GND) TX.4(GND) TX.5(GND) U1.8(VSS) U3.1(GND) U4.2(GND) U5.3(GND) U5.29(GND) U5.30(GND) U8.2(GND) U159.24(GND) U159.26(GND) U159.42(GND) U159.44(GND) U159.48(GND) U159.49(GND) U159.52(GND) U159.53(GND) U159.54(GND) VR3.2 VR4.2 VR5.2 VR7.2 VR8.2 VR9.2 VR10.2 VR11.2 VR12.2 VR13.2
LDO_VIB: C38.1 J4.13 L6.2 U159.23(GPLDO) ; port LDO_VIB
SIM_VDD: C1.1 C3.1 C6.2 J1.4(VCC) R10.2 U159.32(SIM_VDD) VR5.1 ; port SIM_VDD
V_BATTERY: C13.1 C15.2 CON1.1 CON1.2 Q11.3(D) U4.3(BAT) VR8.1 ; port V_BATTERY
VBAT: C11.1 C22.2 C23.2 C33.2 J2.1 J2.2 J3.1 J3.2 R4.2 U159.50(VBAT) U159.51(VBAT)
VBAT_P: C19.2 C34.2 J2.5 J2.6 L2.2 Q11.2(S) R29.2
VBUS: C20.2 C69.2 J3.19 J6.1(VBUS) R13.2 R28.1 R39.2 R47.2 R50.1 U4.4(V+) U5.8(VBUS) U8.3(VIN) VR11.1
VDD: C24.2 R35.1 R40.2 U5.6(VDD) ; port VDD
VDDIO: D5.2 J4.7 R16.2 R38.1 R40.1 U159.46(VDDIO) ; port VDDIO
ADC0: J3.10 R2.2 ; port ADC0
ADC1: J3.11 R9.2 ; port ADC1
BB_ADC0: R2.1 R8.2 U159.13(ADC0) ; port BB_ADC0
BB_ADC1: R9.1 R18.2 U159.14(ADC1) ; port BB_ADC1
CHG_LED: D3.2 U4.1(~{CHRG}) ; port CHG_LED
D+: R34.1 U5.4(D+)
D-: R3.1 U5.5(D-)
GPIO_9: J4.18 U159.18(GPIO_9) ; port GPIO_9
GPIO_13: J3.13 U159.17(GPIO_13) ; port GPIO_13
GPIO_34: J4.19 U159.47(GPIO_34) ; port GPIO_34
GPS_TXD: J3.12 U159.15(GPS_TXD) ; port GPS_TXD
HST_RXD: CON6.1 U159.35(H0ST_RXD) ; port HST_RXD
HST_TXD: CON5.1 U159.36(H0ST_TXD) ; port HST_TXD
LCD_CLK/GPIO_16: J4.4 U159.39(LCD_CLK/GPIO_16) ; port LCD_CLK/GPIO_16
LCD_CS/GPIO_15: J4.3 U159.38(LCD_CS/GPIO_15) ; port LCD_CS/GPIO_15
LCD_DATA/GPIO_17: J4.5 U159.40(LCD_DATA/GPIO_17) ; port LCD_DATA/GPIO_17
LCD_DC/GPIO_18: J4.6 U159.41(LCD_DC/GPIO_18) ; port LCD_DC/GPIO_18
LCD_RST/GPIO_14: J4.8 U159.37(LCD_RST/GPIO_14) ; port LCD_RST/GPIO_14
MIC+: C103.1 C104.2 L1.1 U159.11(MICP) ; port MIC+
MIC-: C103.2 C105.2 L3.1 U159.12(MICN) ; port MIC-
NET_LED/GPIO_28: J3.5 R14.1 U159.2(GPIO_28) ; port NET_LED/GPIO_28
PWRKEY: C2.1 J3.4 JP3.2 JP4.2 S1.3 S1.4 U159.1(PWRKEY) ; port PWRKEY
RESET: C8.1 J4.9 JP1.2 S2.3 S2.4 U159.30(RESET) ; port RESET
SIM_CLK: C4.2 J1.6(CLK) U159.34(SIM_CLK) VR3.1 ; port SIM_CLK
SIM_DAT: C9.2 J1.1(IO) R10.1 U159.33(SIM_DAT) VR7.1 ; port SIM_DAT
SIM_RST: C5.2 J1.5(RST) U159.31(SIM_RST) VR4.1 ; port SIM_RST
SPI1_CLK/GPIO_8: J4.17 U159.19(SPI1_CLK/GPIO_8) ; port SPI1_CLK/GPIO_8
SPI1_CS/GPIO_10: J4.16 U159.20(SPI1_CS/GPIO_10) ; port SPI1_CS/GPIO_10
SPI1_DI/GPIO_12: J4.14 U159.22(SPI1_DI/GPIO_12) ; port SPI1_DI/GPIO_12
SPI1_DO/GPIO_11: J4.15 U159.21(SPI1_DO/GPIO_11) ; port SPI1_DO/GPIO_11
SPK+: L4.2 U159.9(SPKP) ; port SPK+
SPK-: L5.2 U159.10(SPKN) ; port SPK-
UART1_CTS/GPIO_3: J3.8 U159.5(UART1_CTS/GPIO_3/SPI2_DO) ; port UART1_CTS/GPIO_3
UART1_DCD/GPIO_31/WD: J4.11 JP2.2 U159.28(UART1_DCD/GPIO_31) ; port UART1_DCD/GPIO_31/WD
UART1_DTR/GPIO_29: J4.10 U159.29(UART1_DTR/GPIO_29) ; port UART1_DTR/GPIO_29
UART1_RI/GPIO_30: J4.12 JP5.1 U159.27(UART1_RI/GPIO_30) ; port UART1_RI/GPIO_30
UART1_RTS/GPIO_2: J3.9 U159.6(UART1_RTS/GPIO_2/SPI2_CS1) ; port UART1_RTS/GPIO_2
UART1_RXD/GPIO_0: CON6.3 J3.18 R36.1 ; port UART1_RXD/GPIO_0
UART1_TXD/GPIO_1: CON5.3 J3.17 R37.1 ; port UART1_TXD/GPIO_1
UART2_CTS/GPIO_7: J3.6 U159.3(UART2_CTS/GPIO_7/I2C3_SDA) ; port UART2_CTS/GPIO_7
UART2_RTS/GPIO_6: J3.7 U159.4(UART2_RTS/GPIO_6/I2C3_SCL) ; port UART2_RTS/GPIO_6
USB_RXD: CON5.2 U5.25(RXD) ; port USB_RXD
USB_TXD: CON6.2 U5.26(TXD) ; port USB_TXD
VRTC: J4.1 U159.45(VDD_RTC) ; port VRTC
NetC7_1: C7.1 C25.1 R38.2 R39.1 U5.7(REGIN)
NetC10_2: C10.2 C12.2 C14.2 C26.1 D5.1 R12.1 R27.1 R46.1 U1.1(VDD)
NetC16_1: C16.1 U3.6(BST)
NetC16_2: C16.2 R49.2
NetC17_2: C17.2 C18.2 U3.3(VIN) U8.1(VOUT) U8.5(VOUT)
NetC19_1: C19.1 R29.1 R30.2 U3.4(FB)
NetC21_1: C21.1 C37.2 J3.14 L4.1
NetC36_2: C36.2 C37.1 J3.15 L5.1
NetC45_2: C45.2 R11.2 R12.2 U1.4(REST_IN)
NetD1_1: D1.1 R4.1
NetD1_2: D1.2 Q1.3
NetD2_1: D2.1 R16.1
NetD3_1: D3.1 R13.1
NetD4_1: D4.1 U1.5(REST_OUT)
NetD4_2: D4.2 JP1.1
NetGPS1_1: GPS1.1 R5.2
NetJ2_3: J2.3 J2.4 R7.2
NetJ5_1: J5.1 L3.2 VR9.1
NetJ5_2: J5.2 L1.2 VR10.1
NetJ6_2: J6.2(DM) R3.2 VR13.1
NetJ6_3: J6.3(DP) R34.2 VR12.1
NetJ7_2: J7.2(I/O) L6.1 R6.2
NetJP2_1: JP2.1 R46.2 U1.6(WDI)
NetJP3_1: JP3.1 Q2.3
NetJP5_2: JP5.2 R11.1
NetL2_1: L2.1 R49.1 U3.2(SW)
NetQ1_1: Q1.1 R14.2 R15.2
NetQ2_1: Q2.1 R23.2
NetQ11_1: Q11.1(G) R43.1 R47.1
NetR1_2: R1.2 R17.1 TX.1
NetR5_1: R5.1 R6.1 U159.25(GPS_ANT)
NetR17_2: R17.2 R25.1 U159.43(GSM_ANT)
NetR23_1: R23.1 U1.7(POWER_ON_OUT)
NetR25_2: R25.2 R26.2 TP1.1(ANT)
NetR27_2: R27.2 U1.2(WD_EN)
NetR28_2: R28.2 U3.5(EN)
NetR32_1: R32.1 U4.5(PROG)
NetR35_2: R35.2 U5.9(RST)
NetR36_2: R36.2 U159.8(UART1_RXD/GPIO_0/SPI2_CLK)
NetR37_2: R37.2 U159.7(UART1_TXD/GPIO_1/SPI2_CS0)
NetR50_2: R50.2 U8.4(EN)

Not connected (* = marked no-connect by the designer): J1 2(VPP); J6 4(ID); U1 3(RESERVED); U5 1(DCD) 2(RI) 10(NC) 11(SUSPEND) 12(SUSPEND) 13(NC) 14(NC) 15(NC) 16(NC) 17(NC) 18(NC) 19(NC) 20(NC) 21(NC) 22(NC) 23(CTS) 24(RTS) 27(DSR) 28(DTR); U159 16(GPS_RXD)

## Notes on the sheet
- 6
- 5
- 4
- 3
- 2
- 1
- LTR
- ECO NO:
- REVISION RECORD
- APPROVED:
- DATE:
- D
- C
- B
- (near R49) VOUT=4.08V
- A
- COMPANY:
- DRAWN:
- DATED:
- TITLE:
- CHECKED:
- CODE:
- SIZE:
- DRAWING NO:
- REV:
- QUALITY CONTROL:
- RELEASED:
- SCALE:
- SHEET: OF

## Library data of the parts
C1 = CAP-1UF-0402-X5R: CAP CER X5R;1uF;+/-10%;6.3V;0402;0.5mm;ROHS; Manufacture 1 P/N: GRM155R60J105K****;CC0402KRX5R5BB105;C1005X5R0J105KT;JMK105BJ105KV-F;ECJ0EB0J105K;0402X105K6R3CT;CL05A105KQ5NNNC; Manufacture 1: Murata;Yageo;TDK;Taiyo Yuden;Panasonic;Walsin;Samsung; Serial Number: 80214710001; Geometry.Height: 0.55mm
C2 C8 = CAP-0.1UF-0402-X5R-10V: CAP CER X5R/X7R;0.1uF;+/-10%;10V;0402;0.5mm;ROHS; Manufacture 1: Murata;Yageo;Walsin;Eyang; Manufacture 1 P/N: GRM155R61A104K****;GRM155R71A104K****;CC0402KRX5R6BB104;0402X104K100CT;C0402X5R104K100N*; Serial Number: 80214720001
C3 C37 C103 = CAP-100PF-0402-C0G: CAP CER C0G;100PF;+/-5%;50V;0402;0.5mm;ROHS; Manufacture 1: MURATA;TDK;Yageo;Walsin;Eyang; Manufacture 1 P/N: GRM1555C1H101J****;C1005C0G1H101J;CC0402JRNP09BN101;0402N101J500CT;C0402C0G101J500N*; Geometry.Height: 0.55mm; Serial Number: 80214650002
C4-C6 C9 C21 C23 C36 C104 C105 = CAP-33PF-0402-C0G: CAP CER C0G;33PF;+/-5%;50V;0402;0.5mm;ROHS; Manufacture 1: MURATA;Yageo;Eyang; Manufacture 1 P/N: GRM1555C1H330J****;CC0402JRNPO9BN330;C0402C0G330J500N*; Geometry.Height: 0.55mm; Serial Number: 80214650008
C7 C22 = CAP-0.1UF-0402-X7R: CAP CER X7R;0.1uF;+/-10%;16V;0402;0.5mm;ROHS; Manufacture 1: MURATA;Walsin;Yageo;Eyang;; Manufacture 1 P/N: GRM155R71C104K****;0402X104K160CT;CC0402KRX7R7BB104;C0402X5R104K160N*; Geometry.Height: 0.55mm; Serial Number: 80214730006
C10 C12 C14 C17 C18 C34 = CAP-4.7UF-0603-X5R: CAP CER X5R;4.7uF;+/-10%;6.3V;0603;0.8mm;ROHS; Manufacture 1: Murata;TDK;Yageo;Taiyo Yuden;Panasonic;Kyocera;Samsung;; Manufacture 1 P/N: GRM188R60J475K****;C1608X5R0J475K;CC0603KRX5R5BB475;JMK107BJ475KA-T;ECJ1VB0J475K;CV105X5R475K06ATCL10A475KQ8NNNC;; Geometry.Height: 0.95mm; Serial Number: 80216710002
C11 = CAP-AL-1000UF-10.4X10.4: Geometry.Height: 10.4 mm
C13 C20 C25 C69 = CAP-1UF-0402-X5R: CAP CER X5R;1uF;+/-10%;6.3V;0402;0.5mm;ROHS; Manufacture 1: Murata;Yageo;TDK;Taiyo Yuden;Panasonic;Walsin;Samsung; Manufacture 1 P/N: GRM155R60J105K****;CC0402KRX5R5BB105;C1005X5R0J105KT;JMK105BJ105KV-F;ECJ0EB0J105K;0402X105K6R3CT;CL05A105KQ5NNNC; Geometry.Height: 0.55mm; Serial Number: 80214710001; Optional: NF
C15 = CAP-2.2UF-0402-X5R: CAP CER X5R;2.2uF;+/-20%;6.3V;0402;0.5mm;ROHS; Manufacture 1: Murata; Manufacture 1 P/N: GRM155R60J225M****; Geometry.Height: 0.55mm; Serial Number: 80214810001
C16 C24 = CAP-0.1UF-0402-X5R-10V: CAP CER X5R/X7R;0.1uF;+/-10%;10V;0402;0.5mm;ROHS; Manufacture 1: Murata;Yageo;Walsin;Eyang; Manufacture 1 P/N: GRM155R61A104K****;GRM155R71A104K****;CC0402KRX5R6BB104;0402X104K100CT;C0402X5R104K100N*; Geometry.Height: 0.55mm; Serial Number: 80214720001
C19 C38 = CAP-1000PF-0402-X7R: CAP CER X7R;1000PF;+/-10%;50V;0402;0.5mm;ROHS; Manufacture 1 P/N: GRM155R71H102K****;CC0402KRX7R9BB102;0402B102K500CT;C0402X7R102K500N*; Manufacture 1: MURATA;Yageo;Walsin;Eyang; Geometry.Height: 0.55mm; Serial Number: 80214750001
C26 C45 = CAP-0.1UF-0402-X5R-10V: CAP CER X5R/X7R;0.1uF;+/-10%;10V;0402;0.5mm;ROHS; Manufacture 1 P/N: GRM155R61A104K****;GRM155R71A104K****;CC0402KRX5R6BB104;0402X104K100CT;C0402X5R104K100N*; Manufacture 1: Murata;Yageo;Walsin;Eyang; Serial Number: 80214720001; Geometry.Height: 0.55mm
C33 = CAP-18PF-0402-C0G: CAP CER C0G;18PF;+/-5%;50V;0402;0.5mm;ROHS; Manufacture 1: MURATA;Yageo;Eyang; Manufacture 1 P/N: GRM1555C1H180J****;CC0402JRNPO9BN180;C0402C0G180J500N*; Geometry.Height: 0.55mm; Serial Number: 80214650006
CON1 CON4 = DIP2X1-2.54: Geometry.Height: 2mm
CON5 CON6 = DIP3X1-2.54: Geometry.Height: 2mm
D1-D3 = DIODE-LED-BLUE-0603: LED;Blue;3V;LED-0603;0.5mm;ROHS; Manufacture 1 P/N: 19-217/BHC-ZL1M2RY/3T;BL-HB336G-TRB;HT-195NB5;; Manufacture 1: Everlight;佰鸿;Harvatek;; Serial Number: 81230000004
D4 D5 = CDB0130QRM: Schottky Diode;20V;2.0A/0.5V;SMB;4.5*3.9*2.62mm;ROHS; Manufacture 1: Diodes; Manufacture 1 P/N: B220-13-F; Geometry.Height: 0.7mm; Serial Number: 81260000005
GPS1 = DAS1575R25C54: Geometry.Height: 4.7mm
J1 = SIM-CAF99-06183-1503: SIM卡座;6PIN;带横梁;16.4*16.3*1.8mm;ROHS; Manufacture 1 P/N: CAF99-06183-1503;SIM04-6K33210;; Manufacture 1: 乾德电子(原良泽 Linkconn);Singeen(星擎);; Geometry.Height: 1.8mm; Serial Number: 81330000036
J2 = SHW-SPDT: Geometry.Height: 5.5mm
J3 J4 = DIP19X1-2.54: Geometry.Height: 0.05mm
J6 = USO170531D_A5311: Geometry.Height: 2.35mm
J7 = RF-ANT-SOCKET-U.FL-R-SMT: RF CONNECTOR;3*3*1.25mm;ROHS; Manufacture 1: Hirose; Serial Number: 80830000004; Geometry.Height: 1.25mm
JP1-JP5 = RESISTANCE: value: NI/0
L1 L3 = IND-MULT-68NH-0402: IND MULT;68nH;+/-5%;0402;0.6mm;ROHS; Manufacture 1: TDK;Murata;; Manufacture 1 P/N: MLK1005S68NJT;MLG1005S68NJT;LQG15HS68NJ02D;; Geometry.Height: 0.65mm; Serial Number: 80314610003
L2 = MRSC252A12-4R7W-N: Manufacture 1: Chilisin(奇力新); Geometry.Height: 1.2 mm
L4 L5 = BEAD-1000OHM-0402: Bead;1000ohm;250mA;0402;0.6mm;ROHS; Manufacture 1: Murata;Taiyo Yuden;Chilisin(奇力新)();; Manufacture 1 P/N: BLM15HD102SN1;BK1005HS102-T;SBJ100505T-102Y-N; Geometry.Height: 0.65mm; Serial Number: 80334000002
L6 = IND-MULT-33NH-0402-MURATA: IND MULT;33nH;+/-5%;0402;0.6mm;ROHS; Manufacture 1: Murata; Manufacture 1 P/N: LQG15HS33NJ02D; Geometry.Height: 0.65mm; Serial Number: 80314600015
Q1 Q2 = TRIODE-NPN-MMBT3904: Transistor;NPN;40V;200mA;SOT23;1.1mm;ROHS; Manufacture 1: 长电; Serial Number: 81232000008
Q11 = FET-P-AO3415: MOSFET;P-Ch;0.059ohm;4.0A;Vgs=1V;0.75W;SOT-23;1.25mm;ROHS; Manufacture 1 P/N: AO3415;WPM2341-3/TR;; Manufacture 1: AOS;Will(韦尔)();; Serial Number: 81230000014
R1 R5 R6 R11 R17 R25 R26 R38 R40 R49 = RES-0-0402: RES FILM;0;1A;0402;0.4mm;ROHS; Manufacture 1: YAGEO; Manufacture 1 P/N: RC0402JR-070RL; Serial Number: 80114640001
R2 R9 = RES-300K-+/-1%-0402: RES FILM;300K;+/-1%;1/16W;0402;0.4mm;ROHS; Manufacture 1 P/N: RC0402FR-07300KL; Manufacture 1: YAGEO; Serial Number: 80114440041; Geometry.Height: 0.40mm
R3 R34 = RES-33-0402: RES FILM;33;+/-5%;1/16W;0402;0.4mm;ROHS; Manufacture 1 P/N: RC0402JR-0733RL; Manufacture 1: YAGEO; Serial Number: 80114640011
R4 R13 = RES-1K-0402: RES FILM;1K;+/-5%;1/16W;0402;0.4mm;ROHS; Manufacture 1 P/N: RC0402JR-071KL;WR04X102_JTL; Manufacture 1: YAGEO;Walsin; Geometry.Height: 0.40mm; Serial Number: 80114640003
R7 = RES-100-0402: RES FILM;100;+/-5%;1/16W;0402;0.4mm;ROHS; Manufacture 1 P/N: RC0402JR-07100RL;WR04X101_JTL; Manufacture 1: YAGEO;Walsin; Serial Number: 80114640022
R8 R18 = RES-200K-+-1%-0402: RES FILM;200K;+/-1%;1/16W;0402;0.4mm;ROHS; Manufacture 1: YAGEO; Manufacture 1 P/N: RC0402FR-07200KL; Geometry.Height: 0.40mm; Serial Number: 80114440047; Tolerance: 1%
R10 R14 R35 = RES-4.7K-0402: RES FILM;4.7K;+/-5%;1/16W;0402;0.4mm;ROHS; Manufacture 1: YAGEO; Manufacture 1 P/N: RC0402JR-074K7L; Serial Number: 80114640017
R12 R27 R46 = RES-10K-0402: RES FILM;10K;+/-5%;1/16W;0402;0.4mm;ROHS; Manufacture 1 P/N: RC0402JR-0710KL;WR04X103_JTL; Manufacture 1: YAGEO;Walsin; Serial Number: 80114640004
R15 R43 R50 = RES-10K-0402: RES FILM;10K;+/-5%;1/16W;0402;0.4mm;ROHS; Manufacture 1: YAGEO;Walsin; Manufacture 1 P/N: RC0402JR-0710KL;WR04X103_JTL; Serial Number: 80114640004
R16 R36 R37 = RES-510-0402: RES FILM;510;+/-5%;1/16W;0402;0.4mm;ROHS; Manufacture 1: YAGEO; Manufacture 1 P/N: RC0402JR-07510RL; Serial Number: 80114640014
R23 = RES-20K-+/-5%-0402: RES FILM;20K;+/-5%;1/16W;0402;0.4mm;ROHS; Manufacture 1: YAGEO; Manufacture 1 P/N: RC0402JR-0720KL; Serial Number: 80114640009
R28 = RES-100K-0402: RES FILM;100K;+/-5%;1/16W;0402;0.4mm;ROHS; Manufacture 1: YAGEO;Walsin; Manufacture 1 P/N: RC0402JR-07100KL;WR04X104_JTL;; Geometry.Height: 0.40mm; Serial Number: 80114640005
R29 = RES-82K-+-1%-0402: RES FILM;82K;+/-1%;1/16W;0402;0.4mm;ROHS; Manufacture 1: YAGEO; Manufacture 1 P/N: RC0402FR-0782KL; Serial Number: 80114440040
R30 = RES-20K-+/-1%-0402: RES FILM;20K;+/-1%;1/16W;0402;0.4mm;ROHS; Manufacture 1 P/N: RC0402FR-0720KL; Manufacture 1: YAGEO; Serial Number: 80114440008
R32 = RES-3.3K-0402: RES FILM;3.3K;+/-5%;1/16W;0402;0.4mm;ROHS; Manufacture 1: YAGEO; Manufacture 1 P/N: RC0402JR-073K3L; Serial Number: 80114640012
R39 = RES-0402-NF: NF; Geometry.Height: 0.4mm; Tolerance: +/-5%
R47 = RES-1K-0402: RES FILM;1K;+/-5%;1/16W;0402;0.4mm;ROHS; Manufacture 1: YAGEO;Walsin; Manufacture 1 P/N: RC0402JR-071KL;WR04X102_JTL; Serial Number: 80114640003; Geometry.Height: 0.40mm
S1 S2 = IT-1157P: Geometry.Height: 3.1 mm
TX = SMAVERT: SMA Vertical Female Connector; Manufacturer: TE Connectivity; Manufacturer Part Number: 5-1814832-1; Value: 5-1814832-1
U1 = EM78P153B-SOP8-WD: EM78P153B-SOP8; Manufacture: ELAN; Geometry.Height: 1.75mm
U3 = JW5033H: Geometry.Height: 1.1mm
U4 = POWER-CHARGER-SGM4054: 金艺用; Geometry.Height: 1.25mm
U5 = USB-RS232-CP2102: usb trasiver 3.3v 28pin 5*5mm; Manufacture 1 P/N: CP2102-GM; Manufacture 1: Silabs;; Geometry.Height: 1mm; Serial Number: 81700000004
U8 = SGM2554A: LDO;3.3V;300mA;SOT23-5;1.3mm;ROHS; Manufacture 1: PAM; Manufacture 1 P/N: PAM3101DAB330; Geometry.Height: 1.3; Serial Number: 80700000025
U159 = AIR800: Geometry.Height: 2.3 MM
VR3-VR5 VR7-VR13 = ESD-TVS-UM5079: TVS;7V;65pf;SOD882;ROHS; Manufacture 1: Union;韦尔;; Manufacture 1 P/N: ESD9X7V-2/TR;UM5079; Serial Number: 81121000008; Geometry.Height: 0.55mm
